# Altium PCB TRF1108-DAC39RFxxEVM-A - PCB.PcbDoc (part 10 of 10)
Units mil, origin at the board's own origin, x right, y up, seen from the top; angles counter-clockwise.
Board outline 4951.22 x 2726.56 mil, 16 copper layers (Top Layer, L2 GND1, L3 PWR1, L4 GND2, L5 PWR2, L6 GND3, L7 Ctrl Signal 1, L8 GND4, L9 GND5, L10 Ctrl Signal 2, L11 GND6, L12 PWR3, L13 GND7, L14 PWR4, L15 GND8, Bottom Layer), stack 80.2 mil thick; 705 components, 433 nets, 3633 pads, 1678 vias.
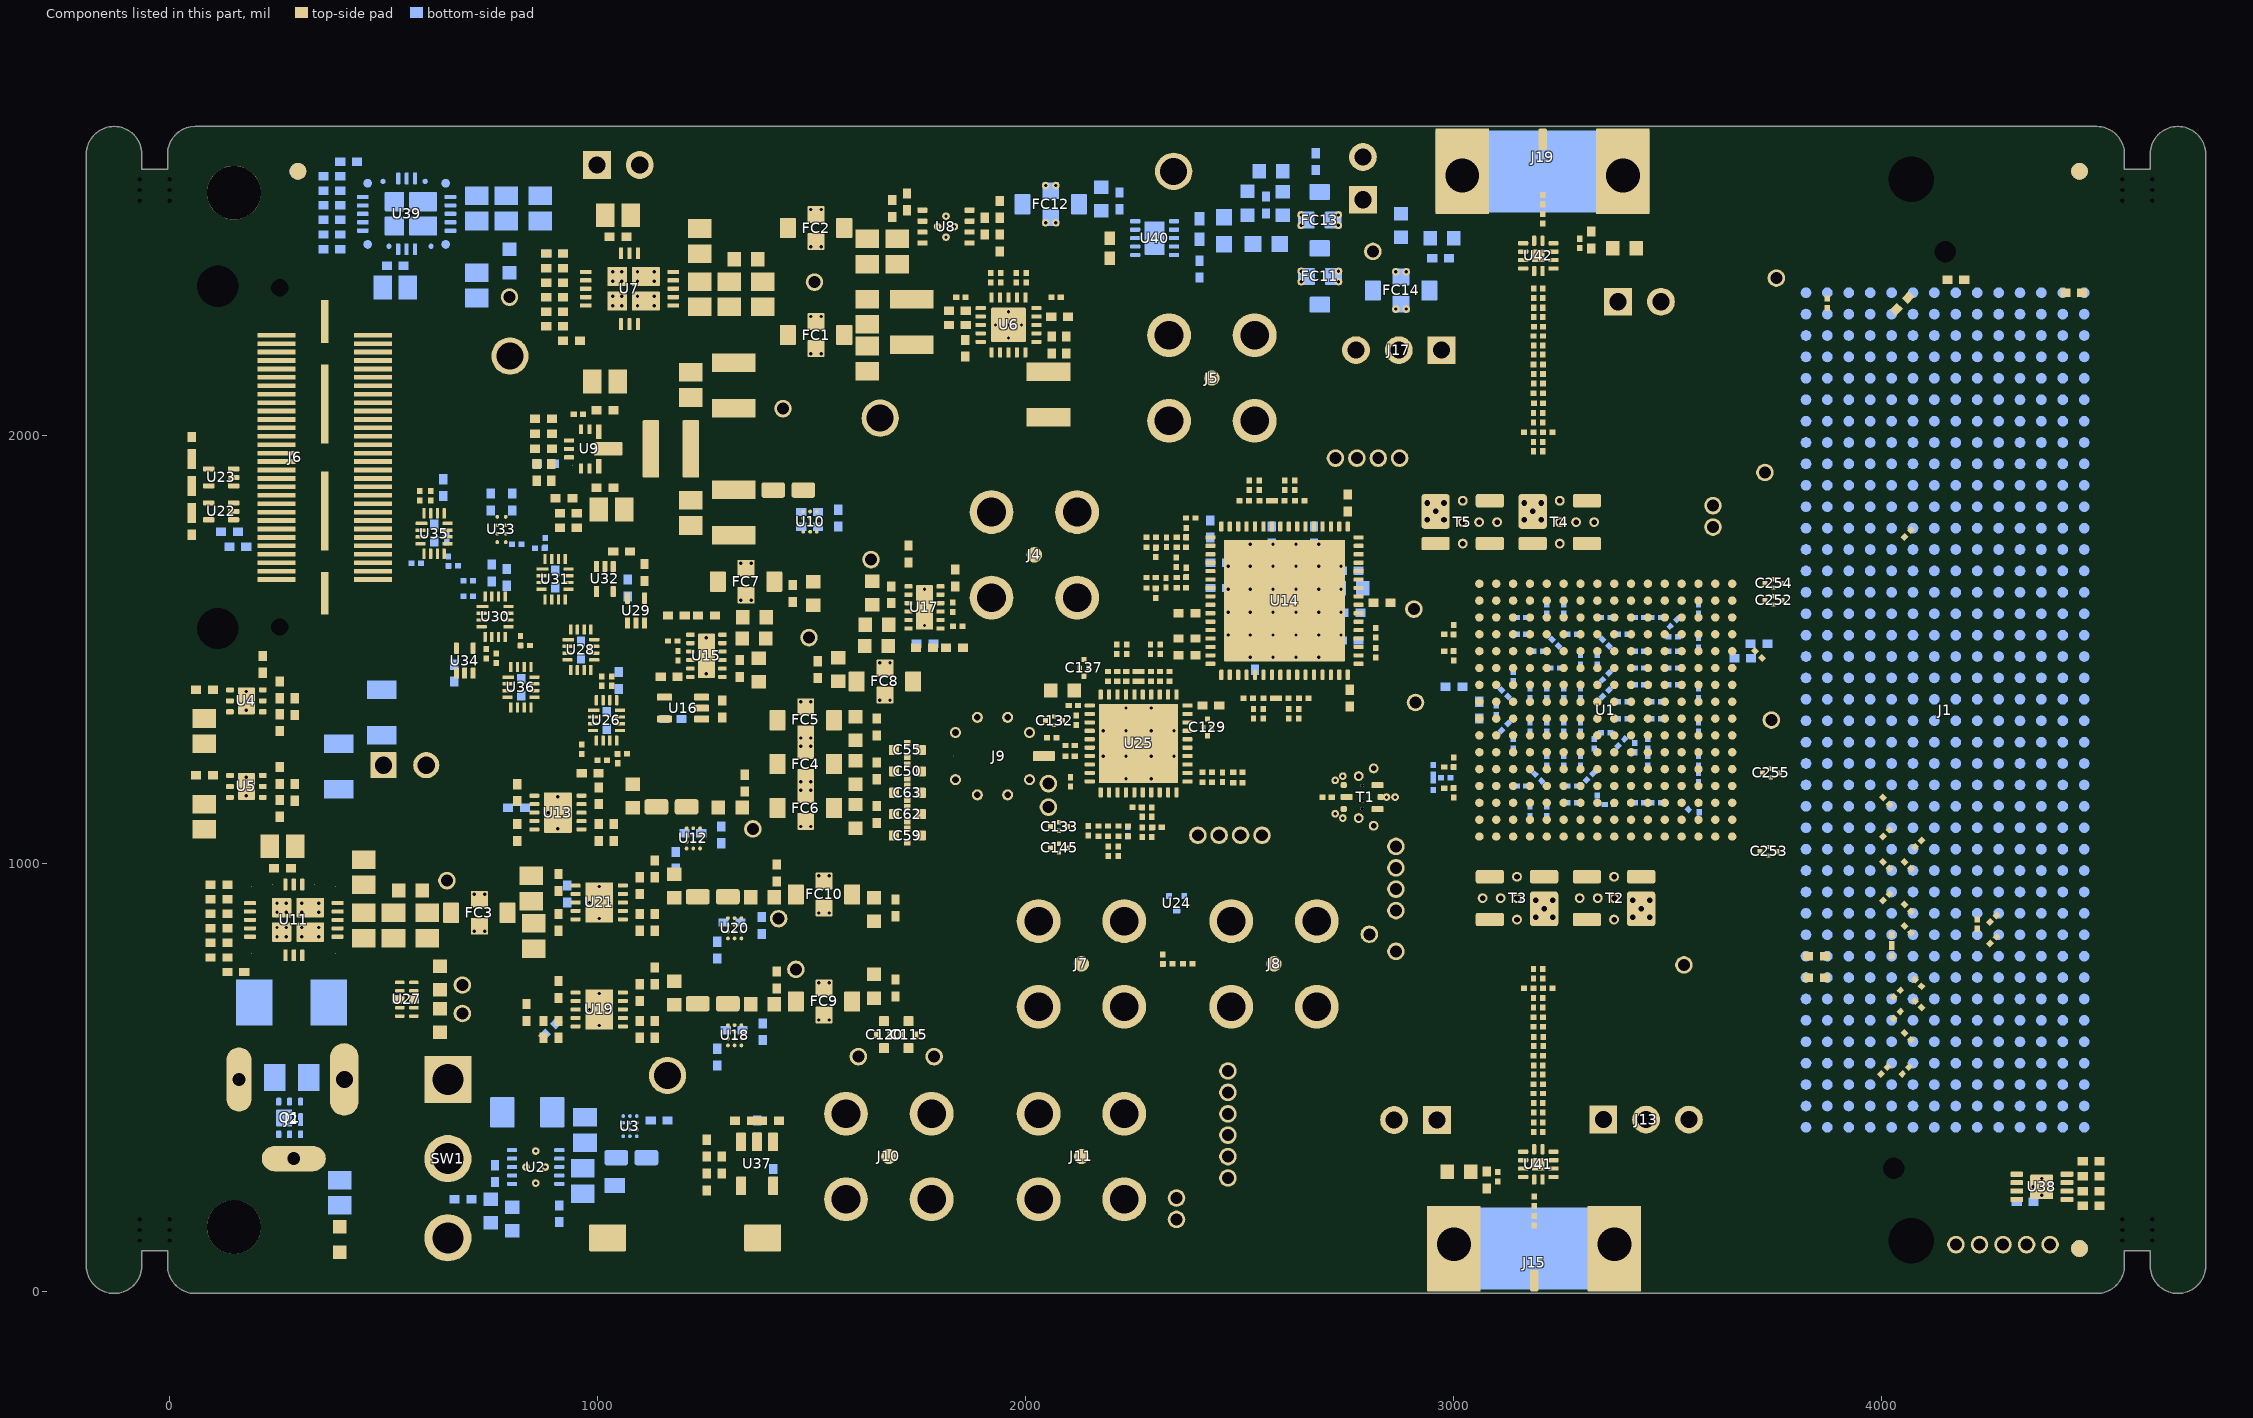
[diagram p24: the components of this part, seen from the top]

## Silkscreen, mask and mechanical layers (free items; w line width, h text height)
Top Overlay:
  lines w5: 1421.37,1569.44 1432.85,1557.95 1432.85,1508.72 ; 1497.99,1407.16 1508.32,1407.16 1510,1408.84 ; 1523.86,1520.73 1535.11,1520.73 1543.43,1529.05 ; 1848.55,1597.9 1873.98,1572.46 1873.98,1569.44 ; 2172.98,1419.4 2172.98,1464.4 2342.98,1464.4 ; 2242.76,1684.39 2254.63,1672.52 2264.21,1672.52 ; 2302.98,1984.4 2237.98,1984.4 2237.98,1909.4 2366.38,1909.4 ; 2372.98,1984.4 2482.98,1984.4 ; 2509.92,1909.4 2572.98,1909.4 2572.98,1984.4
  lines w6: 825.98,2352.4 845.98,2332.4 845.98,2259.4 854.98,2250.4 ; 3267.77,1965.4 3381.98,1965.4 3450.98,1896.4 3481.98,1896.4 ; 3296.89,2417.68 3307.19,2407.39 3307.19,2254.13 ; 3321.64,566.05 3487.05,566.05 3565.65,644.66 3632.53,644.66
  lines w7: 978.99,250.67 1165.44,250.67 ; 1974.16,1100.38 1998.36,1100.38 2024.75,1126.77 ; 2009.03,1126.77 2024.75,1126.77 ; 2024.75,1110 2024.75,1126.77 ; 2533.69,984.3 2533.69,1034.3 ; 2627.9,292.27 2681.61,292.38 ; 2629.25,342.38 2681.61,342.44 ; 2629.25,392.38 2681.61,392.43 ; 2791.92,912.21 2841.92,912.21 ; 2847.55,1979.23 2847.55,2029.23
  text "GND" at 2855.95,2642.27 h30
  text "Uninstalled=USB/Ext / Installed=FMC" at 1200,2600.51 h30
  text "5V" at 2853.2,2528.27 h30
  text "EVM  / Comms" at 450,2477.54 h50
  text "HSC1733" at 4174.55,2456.29 h50
  text "3P3V" at 2769.43,2275.32 h30 r90
  text "GND" at 2978.76,2275.32 h30 r90
  text "PD" at 2850.58,2270.37 h30 r90
  text "DAC39RFXX_TRF11XX_EVM / REVA   AMPS214" at 3643,2115 h44
  text "A" at 2240.96,1993.8 h30
  text "LMK" at 2923.65,1630.22 h30 r90
  text "A" at 2251.96,1474.76 h30
  text "LMX" at 2586,1051 h30
  text "DAC" at 2934,946 h30 r90
  text "SYNC" at 3856.18,817.26 h30
  text "PD" at 3460,477.75 h30 r90
  text "3P3V" at 3566.37,475.28 h30 r90
  text "GND" at 3360.62,474.87 h30 r90
  text "FMC SPI" at 2437.81,298.97 h30 r90
  text "FPGA GPIO" at 4156,46 h30
  text ".Layer_Name" at 750,-1333.99 h60
Bottom Overlay:
  circle w6: c3516.16,1203.77 r25
  circle w6: c1910.4,1143.27 r25
  circle w6: c2215.82,1930.09 r25
  circle w6: c3588.29,1455.01 r25
  lines w6: 294,2291 294,2563 333,2602 336,2602 337,2603 ; 1652.6,1963.18 1652.6,1810.66 1851.56,1810.66 ; 1652.6,2117.3 1652.6,2295.62 1673.91,2295.62 2289.52,2295.62 ; 1984.09,1810.66 2059.45,1810.66 ; 2203.99,1810.66 2325.25,1810.66 2325.25,1942.14 ; 2324.65,2097.08 2325.25,2153.75 ; 3080,1625 3635,1625 3635,1616.55 ; 1358.53,1164.2 1440.79,1164.2 1440.79,966.16 2011.16,966.16 2011.16,1437.26 2007.25,1437.26 1358.53,1437.26 1358.53,1164.2
  lines w7: 2504.64,290.77 2554.64,290.77 ; 2505.29,341.32 2555.29,341.32 ; 2505.29,391.42 2555.29,391.42 ; 2575,1095 2575,1145 ; 2785,915 2835,915 ; 2891,1981 2891,2031 ; 3080,1625 3080,1325 ; 3085,1325 3105,1325 3135,1355 3595,1355 3635,1355 ; 3095,1325 3080,1325 ; 3635,1616.55 3635,1355 ; 3080,1325 3080,1109.76 3080,1083.66 3635,1083.66 3635,1109.76 3635,1355
  text "A" at 2225.67,1915.66 h30
  text "LMK" at 2845.34,1880.38 h30
  text "A" at 3598.14,1440.58 h30
  text "B" at 3523.93,1188.96 h30
  text "B" at 1918.82,1128.28 h30
  text "LMX" at 2519,996 h30
  text "DAC" at 2901,941 h30 r270
  text "FMC SPI" at 2406,296 h30 r270
  text ".Layer_Name" at 577,-1358.49 h60
Top Paste:
  text ".Layer_Name" at 577,-1358.49 h60
Bottom Paste:
  text ".Layer_Name" at 577,-1358.49 h60
Top Solder:
  drawing of 40 lines, arcs and shapes, not listed
  text ".Layer_Name" at 577,-1358.49 h60
  text ".Layer_Name" at 577,-1358.49 h60
Bottom Solder:
  rectangle: 2957.44,1192.08 2965.94,1208.5
  region: 3403.51,1495.98 3403.72,1496.19 3419.73,1496.19 3419.73,1489.55 3414.36,1484.18 3403.5,1495.04 3403.5,1496.08
  text ".Layer_Name" at 577,-1358.49 h60
Drill Guide:
  text ".Layer_Name" at 797.87,-1357.4 h60
M1 Board Outline:
  lines w10: -130,0 ccw(c-130,60) -70,60 ; -130,2716.54 cw(c-130,2656.54) -70,2656.54 -70,2616.54 0,2616.54 0,2656.54 cw(c60,2656.54) 60,2716.54 4501.81,2716.54 cw(c4501.81,2656.53) 4561.81,2656.53 4561.81,2616.54 4631.81,2616.54 4631.81,2656.54 cw(c4691.81,2656.54) 4691.81,2716.54 ; -129.69,0 cw(c-129.69,60) -189.69,60 -189.69,2656.54 cw(c-129.69,2656.54) -129.69,2716.54 ; 4691.5,0 ccw(c4691.5,60) 4751.5,60 4751.5,2656.54 ccw(c4691.5,2656.54) 4691.5,2716.54 ; 4691.81,0 cw(c4691.81,60) 4631.81,60 ; -70,60 -70,100 0,100 0,60 ccw(c60,60) 60,0 4501.81,0 ccw(c4501.81,60) 4561.81,60 4561.81,100 4631.81,100 4631.81,60 ; -70,60 -70,60 ; -70,2529.73 -70,186.81 0,186.81 0,2529.73 -70,2529.73 ; -70,2529.73 -70,2529.73 ; 4631.81,60 4631.81,60 ; 4561.81,186.81 4561.81,2529.73 4631.81,2529.73 4631.81,186.81 4561.81,186.81
  text ".Layer_Name" at 577,-1358.49 h60
M2 Board Dimensions:
  rectangle: 63.78,-725 188.78,-600
  rectangle: 188.78,-850 563.78,-725
  lines w7: 63.78,-725 1063.78,-725 ; 188.78,-850 188.78,-600 ; 313.78,-850 313.78,-600 ; 563.78,-850 563.78,-600 ; 813.78,-850 813.78,-600 ; 63.78,-850 63.78,-600 1063.78,-600 1063.78,-850 63.78,-850
  text ".Layer_Name" at 577,-1358.49 h60
M3 3D STEP Top:
  text ".Layer_Name" at 577,-1358.49 h60
M4 3D STEP Bottom:
  text ".Layer_Name" at 577,-1358.49 h60
M5 Assembly Top:
  lines w10: -292,-1430.17 6308,-1430.17 ; -292,-1226.83 6310,-1226.83 ; -292,-1023.5 -292,-1633.5 3713,-1633.5 6310,-1633.5 6310,-1023.5 -291.5,-1023.5 -291.5,-1633.5 1284,-1633.5 ; 2173,-1633.5 2173,-1023.5 ; 3440,-1226.83 3440,-1023.5 ; 4280,-1226.83 4280,-1023.5 ; 4902,-1640 4902,-1437.17
  text "COMPONENTS MARKED 'DNP' SHOULD NOT BE POPULATED." at 1153.5,-818.5 h60
  text "ASSEMBLY VARIANT:" at 1153,-934 h60
  text ".VariantName" at 2189,-934 h60
  text "PCB VIEWED FROM TOP SIDE" at -228.5,-1155.67 h60
  text "BOARD #:" at 2248,-1155.67 h60
  text ".PRJ_Number" at 2793.5,-1155.67 h60
  text "REV:" at 3638,-1155.67 h60
  text ".PCB_Rev" at 3929.5,-1155.67 h60
  text "SVN REV:" at 4476,-1155.67 h60
  text ".VersionControl_RevNumber" at 4982,-1155.67 h60
  text "PLOT NAME =" at -228.5,-1564.34 h60
  text ".plot_File_Name" at 577,-1564.34 h60
  text "GENERATED    :" at 2250,-1564.34 h60
  text ".Print_Date" at 3119.5,-1564.34 h60
  text ".Print_Time" at 3848.5,-1564.34 h60
  text "TEXAS INSTRUMENTS" at 5113,-1564.34 h60
M6 Assembly Bottom:
  circle w10: c461.16,2587.83 r9.05
  lines w10: -292.5,-1227.33 6309.5,-1227.33 ; -290.5,-1430.67 6309.5,-1430.67 ; 1115.5,-1640.5 1115.5,-1437.67 ; 1737.5,-1227.33 1737.5,-1024 ; 2577.5,-1227.33 2577.5,-1024 ; 3844.5,-1634 3844.5,-1024 ; 4733.5,-1634 6309,-1634 6309,-1024 -292.5,-1024 -292.5,-1634 2304.5,-1634 6309.5,-1634 6309.5,-1024
  text "U24" at 2336.09,901.66 h12
  text "COMPONENTS MARKED 'DNP' SHOULD NOT BE POPULATED." at 6102,-818 h60
  text ".VariantName" at 5058,-934 h60
  text "ASSEMBLY VARIANT:" at 6097,-934 h60
  text ".VersionControl_RevNumber" at 1035.5,-1156.17 h60
  text "SVN REV:" at 1541.5,-1156.17 h60
  text ".PCB_Rev" at 2088,-1156.17 h60
  text "REV:" at 2379.5,-1156.17 h60
  text ".PRJ_Number" at 3224,-1156.17 h60
  text "BOARD #:" at 3769.5,-1156.17 h60
  text "PCB VIEWED FROM BOTTOM SIDE" at 6246,-1156.17 h60
  text "TEXAS INSTRUMENTS" at 904.5,-1564.84 h60
  text ".Print_Time" at 2169,-1564.84 h60
  text ".Print_Date" at 2898,-1564.84 h60
  text "GENERATED    :" at 3767.5,-1564.84 h60
  text ".plot_File_Name" at 5440.5,-1564.84 h60
  text "PLOT NAME =" at 6246,-1564.84 h60
M9 Title Sheet:
  drawing of 56 lines, arcs and shapes, not listed
  text "1" at -941.66,11381.39 h70
  text "2" at 2384,11381.39 h70
  text "3" at 5714,11381.39 h70
  text "4" at 9049,11381.39 h70
  text "5" at 12374,11381.39 h70
  text "6" at 15709,11381.39 h70
  text "A" at -2463,9603.39 h70
  text "A" at 17237,9603.39 h70
  text "B" at -2463,5853.39 h70
  text "B" at 17237,5853.39 h70
  text "C" at -2463,2103.39 h70
  text "C" at 17237,1906.54 h70
  text ".Layer_Name" at 577,-1358.49 h60
  text "D" at -2463,-1646.61 h70
  text "D" at 17237,-1646.61 h70
  text "PROJECT TITLE:" at 14143,-1731.61 h45
  text ".PRJ_Title" at 14193,-1864.94 h70
  text "DESIGNED FOR:" at 14143,-2032.61 h45
  text ".PRJ_Customer" at 14193,-2172.61 h70
  text "FILE NAME:" at 14143,-2332.61 h45
  text ".PCB_File_Name_No_Path" at 14193,-2452.61 h70
  text "Texas Instruments (TI) and/or its licensors do not warrant the accuracy or completeness of this specification" at 9173.5,-2614.45 h45
  text "ENGINEER:" at 14143,-2622.61 h45
  text "LAYOUT BY:" at 15648,-2622.61 h45
  text "or any information contained therein. TI and/or its licensors do not warrant that this design will meet" at 9128.51,-2727.11 h45
  text ".PRJ_Engineer" at 14193,-2777.6 h70
  text ".PCB_Layout" at 15698.5,-2777.6 h70
  text "the specifications, will be suitable for your application or fit for any particular purpose, or will operate in" at 9128.51,-2839.78 h45
  text "ALTIUM DESIGNER VERSION:" at 15648,-2932.61 h45
  text "an implementation. TI and/or its licensors do not warrant that the design is production worthy. You should" at 9128.51,-2952.44 h45
  text "completely validate and test your design implementation to confirm the system functionality for your application." at 9173.5,-3065.11 h45
  text ".print_Scale" at 14193,-3065.94 h70
  text ".Application_BuildNumber" at 15698.5,-3065.94 h70
  text "1" at -941.66,-3318.61 h70
  text "2" at 2384,-3318.61 h70
  text "3" at 5714,-3318.61 h70
  text "4" at 9049,-3318.61 h70
  text "5" at 12374,-3318.61 h70
  text "6" at 15709,-3318.61 h70
M10 Fab Notes:
  drawing of 246 lines, arcs and shapes, not listed
  text "NOTES: (UNLESS OTHERWISE SPECIFIED)" at -480.84,8498.11 h100
  text "1.FABRICATE PER IPC-6012A CLASS 2" at -480.84,8272.82 h100
  text "2.LAMINATE MATERIAL: MEGTRON6 & FR4-370HR" at -480.84,8047.53 h100
  text "IMPEDANCE TABLE" at 10010,8010 h100
  text "3.COPPER WEIGHT: SEE STACKUP" at -480.84,7822.24 h100
  text "SINGLE ENDED (50 OHM)" at 9760,7800 h60
  text "DIFF PAIR (100 OHM)" at 11650,7800 h60
  text "LAYERS" at 8799.36,7688.62 h60
  text "WIDTH" at 9848.99,7598.29 h60
  text "TOLERANCE" at 10628.48,7598.29 h60
  text "WIDTH/GAP" at 11550,7598.29 h60
  text "TOLERANCE" at 12429.48,7598.29 h60
  text "4.BOARD THICKNESS: 2MM +/- 10%" at -480.84,7580.29 h100
  text "TOP LAYER" at 8735.63,7396.99 h55
  text "10 MIL" at 9848.99,7385.33 h60
  text "6.25 MIL /3.5 MIL" at 11300,7385.33 h60
  text "+/-10%" at 10695.3,7380.33 h60
  text "+/-10%" at 12496.3,7380.33 h60
  text "5.NO OF LAYERS: 16 AS PER SUPPLIED ARTWORK" at -480.84,7355 h100
  text "L10 CTRL SIGNAL 2" at 8520.28,7190 h55
  text "-----" at 9848.99,7187.5 h60
  text "4 MIL /5 MIL" at 11439.95,7187.5 h60
  text "-----" at 10695.3,7182.5 h60
  text "+/-10%" at 12496.3,7182.5 h60
  text "6.SURFACE FINISH: ENIG" at -480.84,7129.71 h100
  text "BOTTOM LAYER" at 8662.32,7000 h55
  text "10 MIL" at 9848.99,6988.34 h60
  text "6.25 MIL /3.5 MIL" at 11300,6988.34 h60
  text "+/-10%" at 10700.29,6983.34 h60
  text "+/-10%" at 12496.3,6983.34 h60
  text "7.SOLDERMASK BOTH SIDES WITH LIQUID PHOTO IMAGEABLE (LPI) PER IPC-SM-840C" at -480.84,6904.42 h100
  text "COLOR:RED" at -480.84,6679.13 h100
  text "8.SILKSCREEN: BOTH SIDE WITH PERMANENT NON CONDUCTIVE WHITE EPOXY INK." at -480.84,6453.84 h100
  text "SILKSCREEN MAY BE TRIMMED OFF ANY SOLDERED ENTITY." at -480.84,6228.55 h100
  text "M10 Fab Notes" at 14099.69,6057.1 h60
  text "9.BOW AND TWIST NOT TO EXCEED 0.180MM (0.007\") PER INCH AS MEASURED PER IPC-TM-650." at -480.84,5986.6 h100
  text "DESIGN INFORMATION" at 15178.02,5939.98 h60
  text "MIN. TRACK WIDTH:" at 14533.46,5807.85 h60
  text "4" at 15629.7,5807.85 h60
  text "MIL" at 15784.46,5807.85 h60
  text "10.SOLDER MASK CLEARANCE IS GIVEN SAME AS PAD SIZE EXCEPT FOR NPTH AND FIDUCIALS." at -480.84,5761.32 h100
  text "MIN. CLEARANCE:" at 14533.46,5683.73 h60
  text "MIL" at 15784.46,5683.73 h60
  text "3.5" at 15575,5675 h60
  text "MIN. VIA PAD SIZE:" at 14533.46,5559.6 h60
  text "18" at 15599.71,5559.6 h60
  text "MIL" at 15784.46,5559.6 h60
  text "VENDOR SHALL OVERSIZE THE MASK CLEARANCES AS PER THE REQUIRED  MANUFACTURING CAPABILITIES," at -480.84,5536.03 h100
  text "0.05mm (2MIL)" at 15228.46,5429.7 h60
  text "MINIMUM ANNULAR RING" at 14204.23,5421.48 h60
  text "EXTERNAL" at 15936.46,5421.48 h60
  text "PER" at 14404.23,5311.35 h60
  text "IPC-D-275 CLASS 2 LEVEL C" at 14624.23,5311.35 h60
  text "11.100% CONTINUITY TESTING USING DATABASE NETLIST SHALL BE PERFORMED." at -493.74,5246.14 h100
  text "MIL, HOLES" at 16112.46,5210.87 h60
  text "+/-" at 15720,5202.29 h60
  text "+/-" at 16574,5202.29 h60
  text "REGISTRATION TOLERANCES:" at 14204.23,5201.22 h60
  text "METAL" at 15404,5201.22 h60
  text "5" at 15980.2,5201.22 h60
  text "3" at 16813.2,5201.22 h60
  text "MIL" at 16929.46,5201.22 h60
  text "HOLE SIZE TOLERANCE (UNLESS OTHERWISE SPECIFIED):" at 14204.23,5102.91 h60
  text "+/-" at 16574,5100.03 h60
  text "3" at 16813.2,5098.97 h60
  text "MIL" at 16929.46,5098.97 h60
  text "12.ALL INNER LAYER UNCONNECTED PADS SHALL BE REMOVED." at -493.74,5020.85 h100
  text "MATERIAL:" at 14129.46,4961.32 h60
  text "ISOLA FR4-370HR (or Equivalent)" at 15115.9,4832.8 h60
  text "X" at 14971.46,4824.81 h60
  text "FR-408" at 14550.46,4819.15 h60
  text "13.LOCAL FIDUCIALS MUST BE FREE OF ANY MARKINGS." at -493.74,4795.56 h100
  text "Isola I-Speed" at 15115.9,4635.95 h60
  text "Meg4" at 14550.46,4623.44 h60
  text "14.ALL VIAS ARE REQUIRED NON-CONDUCTIVE FILL AND PLATED OVER ON BOTH SIDES EXCEPT 10.1 MIL DRILL VIAS. UNLESS OTHERWISE MASK IS OPENED IN GERBERS" at -493.74,4570.28 h100
  text "X" at 14415.9,4440.64 h60
  text "Meg6 (or Equivalent)" at 14550.46,4426.59 h60
  text "15.BOARD DIMENSION: 115.87 MM X 69 MM." at -493.74,4344.99 h100
  text "OTHER" at 14590.46,4229.74 h60
  text "62 MIL (1.6mm) +/-10%" at 14870.56,4086.71 h60
  text "81 MIL  +/-10%" at 16446.53,4086.71 h60
  text "X" at 16040.7,4082.23 h60
  text "THICKNESS:" at 14204.23,4078.49 h60
  text "OTHER" at 16155.46,4078.49 h60
  text "TOLERANCE:" at 14204.23,3940.17 h60
  text "X" at 15052.46,3940.17 h60
  text "ANSI IPC-6012 TYPE 3 CLASS 2" at 15230.48,3940.17 h60
  text "OTHER +/-" at 15230.46,3795.99 h60
  text "BOW & TWIST:" at 14204.23,3650.8 h60
  text "X" at 15052.46,3650.8 h60
  text "ANSI IPC-6012 TYPE 3 CLASS 2" at 15230.48,3650.8 h60
  text "OTHER +/-" at 15230.46,3504.1 h60
  text "DRILLING:" at 14129.46,3373.48 h60
  text "NC_DRILL FILES" at 15890.46,3268.29 h60
  text "REFERENCE:" at 14204.23,3264.36 h60
  text "X" at 14861.46,3264.26 h60
  text "AS SHOWN" at 15039.46,3264.36 h60
  text "X" at 15762.46,3264.36 h60
  text "OTHER" at 16188.46,3122.1 h60
  text "PTH COPPER THICKNESS:" at 14203.91,3118.57 h60
  text "X" at 15343.14,3118.57 h60
  text "20-30 um" at 15471.14,3118.57 h60
  text "BOARD FINISH:" at 14129.46,2970.98 h60
  text "SILKSCREEN:" at 14284.68,2860.85 h60
  text "X" at 15242.46,2860.85 h60
  text "TOP" at 15359.46,2860.85 h60
  text "X" at 15752.46,2860.85 h60
  text "BOTTOM" at 15870.46,2860.85 h60
  text "X" at 15752.71,2709.61 h60
  text "WHITE" at 16227.99,2706.26 h60
  text "SILKSCREEN COLOR:" at 14284.68,2705.66 h60
  text "WHITE" at 15359.46,2705.66 h60
  text "OTHER" at 15870.46,2705.66 h60
  text "RED" at 16476.25,2568.34 h60
  text "X" at 15965.14,2565.63 h60
  text "GREEN" at 15490.46,2562.21 h60
  text "OTHER" at 16108.46,2562.21 h60
  text "SOLDER RESIST COLOR:" at 14284.68,2555.35 h60
  text "X" at 15372.46,2407.96 h60
  text "MATTE" at 15490.46,2407.96 h60
  text "SEMI-GLOSS" at 16108,2407.32 h60
  text "IMMERSION GOLD (ENIG)" at 15190.46,2235.19 h60
  text "ENEPIG" at 16528,2227.97 h60
  text "SURFACE FINISH:" at 14129.46,2226.97 h60
  text "X" at 15012.46,2226.97 h60
  text "IMM. TIN/SILVER OR EQUIV" at 14459,2089.65 h60
  text "HARD GOLD (30u)" at 15890.46,2085.72 h60
  text "OTHER" at 14484,1888.87 h60
  text "ARRAY/PANEL:" at 14129.46,1733.49 h60
  text "CUT AND TRIM PER M1 BOARD OUTLINE" at 15190.46,1725.27 h60
  text "N.C. ROUTE" at 15190.46,1589.3 h60
  text "X" at 15878.46,1589.3 h60
  text "V. SCORE" at 16056.46,1589.3 h60
  text "CERTIFICATION:" at 14129.46,1460.17 h60
  text "MATERIALS AND WORKMANSHIP FOR ALL PCBS" at 14854.46,1460.17 h60
  text "TO MEET OR EXCEED THE REQUIREMENTS OF:" at 14854.46,1366.11 h60
  text "X" at 14491.97,1237.48 h60
  text "ANSI IPC-A-600F CLASS ->" at 14619.96,1237.48 h60
  text "X" at 16267.97,1237.48 h60
  text "2" at 16377.96,1237.48 h60
  text "1" at 16062.96,1235.99 h60
  text "3" at 16731.96,1235.98 h60
  text "X" at 15303.97,1089.8 h60
  text "RoHS" at 15431.96,1089.8 h60
  text "OTHER" at 16076.36,1089.8 h60
  text "PER ORDER" at 16473.42,1089.8 h60
  text "ALL BOARDS MUST MEET OR EXCEED UL94-V0 REQUIREMENTS." at 14157,935.97 h60
  text "PCB MUST BEAR THE UL94V-0 UL REGISTERED MATERIAL ID NUMBER" at 14157,819.91 h60
  text "ADDITIONAL REQUIREMENTS:" at 14129.46,650.48 h60
  text "MICROSECTION:" at 14204.23,543.36 h60
  text "YES" at 15109.96,543.36 h60
  text "REQUIRED" at 15971.46,399.02 h60
  text "BARE BOARD ELEC. TEST:" at 14204.23,396.17 h60
  text "NONE" at 15509.96,396.17 h60
  text "X" at 15853.46,396.17 h60
  text "PER ORDER" at 16563.46,396.17 h60
  text "X" at 14245.08,205.71 h60
  text "16 MIL & SMALLER VIAS REQUIRE NON-CONDUCTIVE FILL AND PLANARIZE" at 14356.3,115.16 h59
  text "X" at 14252.07,10.12 h60
  text "OUTER LAYER TRACKS 10 MIL WIDE REQUIRE 50 OHM SINGLE-ENDED IMPEDANCE" at 14359.25,-95.47 h60
  text "X" at 14250.36,-196.63 h60
  text "OUTER LAYER TRACKS 6.25 MIL WIDE WITH 3.5 MIL AIR GAP REQUIRE 100 OHM DIFFERENTIAL IMPEDANCE" at 14359.25,-300.2 h60
  text "INNER LAYER XX & XX TRACKS XX MIL WIDE REQUIRE 50 OHM SINGLE-ENDED IMPEDANCE" at 14359.25,-504.92 h60
  text "X" at 14245.36,-606.63 h60
  text "INNER LAYER 10 TRACKS 4 MIL WIDE WITH   / 5 MIL AIR GAP REQUIRE 100 OHM DIFFERENTIAL IMPEDANCE" at 14345,-780 h60
  text ".Layer_Name" at 577,-1358.49 h60
M11 Gerber Information:
  lines w10: -292,-1430.17 6308,-1430.17 ; -292,-1226.83 6310,-1226.83 ; -292,-1023.5 -292,-1633.5 3713,-1633.5 6310,-1633.5 6310,-1023.5 -291.5,-1023.5 -291.5,-1633.5 1284,-1633.5 ; 2173,-1633.5 2173,-1023.5 ; 3440,-1226.83 3440,-1023.5 ; 4280,-1226.83 4280,-1023.5 ; 4902,-1640 4902,-1437.17
  text "ALL ARTWORK VIEWED FROM TOP SIDE" at -228.5,-1155.67 h60
  text "BOARD #:" at 2248,-1155.67 h60
  text ".PRJ_Number" at 2793.5,-1155.67 h60
  text "REV:" at 3638,-1155.67 h60
  text ".PCB_Rev" at 3929.5,-1155.67 h60
  text "SVN REV:" at 4476,-1155.67 h60
  text ".VersionControl_RevNumber" at 4982,-1155.67 h60
  text "LAYER NAME =" at -228.5,-1358.49 h60
  text "PLOT NAME =" at -228.5,-1564.34 h60
  text ".plot_File_Name" at 577,-1564.34 h60
  text "GENERATED    :" at 2250,-1564.34 h60
  text ".Print_Date" at 3119.5,-1564.34 h60
  text ".Print_Time" at 3848.5,-1564.34 h60
  text "TEXAS INSTRUMENTS" at 5113,-1564.34 h60
M12 Stackup:
  drawing of 971 lines, arcs and shapes, not listed
  text "Layer" at 9129.39,4130 h60
  text "Name" at 9539.31,4130 h60
  text "Material" at 10629,4130 h60
  text "Thickness" at 11488.77,4130 h60
  text "Constant" at 12138.6,4130 h60
  text "Board Layer Stack" at 12708.46,4130 h60
  text "Top Overlay" at 9539.31,4010 h60
  text "Top Solder" at 9539.31,3890 h60
  text "Solder Resist" at 10629,3890 h60
  text "0.40mil" at 11488.77,3890 h60
  text "3.5" at 12138.6,3890 h60
  text "1" at 9129.39,3770 h60
  text "Top Layer" at 9539.31,3770 h60
  text "1.40mil" at 11488.77,3770 h60
  text "Dielectric 1" at 9539.31,3650 h60
  text "Megtron6" at 10629,3650 h60
  text "4.90mil" at 11488.77,3650 h60
  text "3.34" at 12138.6,3650 h60
  text "2" at 9129.39,3530 h60
  text "L2 GND1" at 9539.31,3530 h60
  text "CF-004" at 10629,3530 h60
  text "1.40mil" at 11488.77,3530 h60
  text "Dielectric 2" at 9539.31,3410 h60
  text "FR4-370HR" at 10629,3410 h60
  text "3.00mil" at 11488.77,3410 h60
  text "3.72" at 12138.6,3410 h60
  text "3" at 9129.39,3290 h60
  text "L3 PWR1" at 9539.31,3290 h60
  text "CF-004" at 10629,3290 h60
  text "1.40mil" at 11488.77,3290 h60
  text "Dielectric 3" at 9539.31,3170 h60
  text "FR4-370HR" at 10629,3170 h60
  text "3.00mil" at 11488.77,3170 h60
  text "3.72" at 12138.6,3170 h60
  text "4" at 9129.39,3050 h60
  text "L4 GND2" at 9539.31,3050 h60
  text "CF-004" at 10629,3050 h60
  text "1.40mil" at 11488.77,3050 h60
  text "Dielectric 4" at 9539.31,2930 h60
  text "FR4-370HR" at 10629,2930 h60
  text "3.00mil" at 11488.77,2930 h60
  text "3.86" at 12138.6,2930 h60
  text "5" at 9129.39,2810 h60
  text "L5 PWR2" at 9539.31,2810 h60
  text "CF-004" at 10629,2810 h60
  text "1.40mil" at 11488.77,2810 h60
  text "Dielectric 5" at 9539.31,2690 h60
  text "FR4-370HR" at 10629,2690 h60
  text "3.00mil" at 11488.77,2690 h60
  text "3.72" at 12138.6,2690 h60
  text "6" at 9129.39,2570 h60
  text "L6 GND3" at 9539.31,2570 h60
  text "CF-004" at 10629,2570 h60
  text "1.40mil" at 11488.77,2570 h60
  text "Dielectric 6" at 9539.31,2450 h60
  text "FR4-370HR" at 10629,2450 h60
  text "3.00mil" at 11488.77,2450 h60
  text "3.86" at 12138.6,2450 h60
  text "7" at 9129.39,2330 h60
  text "L7 Ctrl Signal 1" at 9539.31,2330 h60
  text "CF-004" at 10629,2330 h60
  text "1.40mil" at 11488.77,2330 h60
  text "Dielectric 8" at 9539.31,2210 h60
  text "FR4-370HR" at 10629,2210 h60
  text "3.00mil" at 11488.77,2210 h60
  text "3.72" at 12138.6,2210 h60
  text "Dielectric 7" at 9539.31,2090 h60
  text "FR4-370HR" at 10629,2090 h60
  text "3.00mil" at 11488.77,2090 h60
  text "3.72" at 12138.6,2090 h60
  text "8" at 9129.39,1970 h60
  text "L8 GND4" at 9539.31,1970 h60
  text "CF-004" at 10629,1970 h60
  text "1.40mil" at 11488.77,1970 h60
  text "Dielectric 9" at 9539.31,1850 h60
  text "FR4-370HR" at 10629,1850 h60
  text "6.00mil" at 11488.77,1850 h60
  text "3.86" at 12138.6,1850 h60
  text "9" at 9129.39,1730 h60
  text "L9 GND5" at 9539.31,1730 h60
  text "CF-004" at 10629,1730 h60
  text "1.40mil" at 11488.77,1730 h60
  text "Dielectric 11" at 9539.31,1610 h60
  text "FR4-370HR" at 10629,1610 h60
  text "3.00mil" at 11488.77,1610 h60
  text "3.72" at 12138.6,1610 h60
  text "Dielectric 10" at 9539.31,1490 h60
  text "FR4-370HR" at 10629,1490 h60
  text "3.00mil" at 11488.77,1490 h60
  text "3.72" at 12138.6,1490 h60
  text "10" at 9129.39,1370 h60
  text "L10 Ctrl Signal 2" at 9539.31,1370 h60
  text "CF-004" at 10629,1370 h60
  text "1.40mil" at 11488.77,1370 h60
  text "Dielectric 12" at 9539.31,1250 h60
  text "FR4-370HR" at 10629,1250 h60
  text "3.00mil" at 11488.77,1250 h60
  text "3.86" at 12138.6,1250 h60
  text "11" at 9129.39,1130 h60
  text "L11 GND6" at 9539.31,1130 h60
  text "CF-004" at 10629,1130 h60
  text "1.40mil" at 11488.77,1130 h60
  text "Dielectric 13" at 9539.31,1010 h60
  text "FR4-370HR" at 10629,1010 h60
  text "3.00mil" at 11488.77,1010 h60
  text "3.72" at 12138.6,1010 h60
  text "12" at 9129.39,890 h60
  text "L12 PWR3" at 9539.31,890 h60
  text "CF-004" at 10629,890 h60
  text "1.40mil" at 11488.77,890 h60
  text "Dielectric 14" at 9539.31,770 h60
  text "FR4-370HR" at 10629,770 h60
  text "3.00mil" at 11488.77,770 h60
  text "3.86" at 12138.6,770 h60
  text "13" at 9129.39,650 h60
  text "L13 GND7" at 9539.31,650 h60
  text "CF-004" at 10629,650 h60
  text "1.40mil" at 11488.77,650 h60
  text "Dielectric 15" at 9539.31,530 h60
  text "FR4-370HR" at 10629,530 h60
  text "3.00mil" at 11488.77,530 h60
  text "3.72" at 12138.6,530 h60
  text "14" at 9129.39,410 h60
  text "L14 PWR4" at 9539.31,410 h60
  text "CF-004" at 10629,410 h60
  text "1.40mil" at 11488.77,410 h60
  text "Dielectric 16" at 9539.31,290 h60
  text "FR4-370HR" at 10629,290 h60
  text "3.00mil" at 11488.77,290 h60
  text "3.72" at 12138.6,290 h60
  text "15" at 9129.39,170 h60
  text "L15 GND8" at 9539.31,170 h60
  text "CF-004" at 10629,170 h60
  text "1.40mil" at 11488.77,170 h60
  text "Dielectric 17" at 9539.31,50 h60
  text "Megtron6" at 10629,50 h60
  text "4.90mil" at 11488.77,50 h60
  text "3.34" at 12138.6,50 h60
  text "16" at 9129.39,-70 h60
  text "Bottom Layer" at 9539.31,-70 h60
  text "1.40mil" at 11488.77,-70 h60
  text "Bottom Solder" at 9539.31,-190 h60
  text "Solder Resist" at 10629,-190 h60
  text "0.40mil" at 11488.77,-190 h60
  text "3.5" at 12138.6,-190 h60
  text "Bottom Overlay" at 9539.31,-310 h60
  text "Total board thickness:" at 9129.39,-430 h60
  text "81.00mil" at 11488.77,-430 h60
  text ".Layer_Name" at 577,-1358.49 h60
M13 Component Bodies Top:
  text ".Layer_Name" at 577,-1358.49 h60
M14 Component Bodies Bottom:
  text ".Layer_Name" at 577,-1358.49 h60
M15 Courtyards Top:
  text ".Layer_Name" at 577,-1358.49 h60
M16 Courtyards Bottom:
  text ".Layer_Name" at 577,-1358.49 h60
Drill Drawing:
  drawing of 172 lines, arcs and shapes, not listed
  text "Symbol" at 5817.36,2857.52 h72
  text "Count" at 6117.92,2857.52 h72
  text "Hole Size" at 6450.09,2857.52 h72
  text "Plated" at 7040,2857.52 h72
  text "Hole Type" at 7299.14,2857.52 h72
  text "Drill Layer Pair" at 7674.3,2857.52 h72
  text "Hole Tolerance" at 8398.63,2857.52 h72
  text "194" at 6117.92,2733.2 h60
  text "7.87mil (0.200mm)" at 6450.09,2733.2 h60
  text "PTH" at 7040,2733.2 h60
  text "Round" at 7299.14,2733.2 h60
  text "Top Layer - Bottom Layer" at 7674.3,2733.2 h60
  text "+/-3.00mil" at 8398.63,2733.2 h60
  text "E" at 5792.07,2723.21 h55.25
  text "1479" at 6117.92,2608.88 h60
  text "8.00mil (0.203mm)" at 6450.09,2608.88 h60
  text "PTH" at 7040,2608.88 h60
  text "Round" at 7299.14,2608.88 h60
  text "Top Layer - Bottom Layer" at 7674.3,2608.88 h60
  text "+/-3.00mil" at 8398.63,2608.88 h60
  text "C" at 5792.07,2598.89 h55.25
  text "24" at 6117.92,2484.56 h60
  text "10.00mil (0.254mm)" at 6450.09,2484.56 h60
  text "NPTH" at 7040,2484.56 h60
  text "Round" at 7299.14,2484.56 h60
  text "Top Layer - Bottom Layer" at 7674.3,2484.56 h60
  text "+/-2.00mil" at 8398.63,2484.56 h60
  text "187" at 6117.92,2360.24 h60
  text "10.01mil (0.254mm)" at 6450.09,2360.24 h60
  text "PTH" at 7040,2360.24 h60
  text "Round" at 7299.14,2360.24 h60
  text "Top Layer - Bottom Layer" at 7674.3,2360.24 h60
  text "+/-3.00mil" at 8398.63,2360.24 h60
  text "40" at 6117.92,2235.92 h60
  text "12.99mil (0.330mm)" at 6450.09,2235.92 h60
  text "PTH" at 7040,2235.92 h60
  text "Round" at 7299.14,2235.92 h60
  text "Top Layer - Bottom Layer" at 7674.3,2235.92 h60
  text "+/-3.00mil" at 8398.63,2235.92 h60
  text "4" at 6117.92,2111.6 h60
  text "13.00mil (0.330mm)" at 6450.09,2111.6 h60
  text "PTH" at 7040,2111.6 h60
  text "Round" at 7299.14,2111.6 h60
  text "Top Layer - Bottom Layer" at 7674.3,2111.6 h60
  text "+/-3.00mil" at 8398.63,2111.6 h60
  text "8" at 6117.92,1987.28 h60
  text "15.75mil (0.400mm)" at 6450.09,1987.28 h60
  text "PTH" at 7040,1987.28 h60
  text "Round" at 7299.14,1987.28 h60
  text "Top Layer - Bottom Layer" at 7674.3,1987.28 h60
  text "+/-3.00mil" at 8398.63,1987.28 h60
  text "D" at 5792.07,1977.29 h55.25
  text "51" at 6117.92,1862.96 h60
  text "28.00mil (0.711mm)" at 6450.09,1862.96 h60
  text "PTH" at 7040,1862.96 h60
  text "Round" at 7299.14,1862.96 h60
  text "Top Layer - Bottom Layer" at 7674.3,1862.96 h60
  text "+/-3.00mil" at 8398.63,1862.96 h60
  text "2" at 6117.92,1738.64 h60
  text "29.92mil (0.760mm)" at 6450.09,1738.64 h60
  text "PTH" at 7040,1738.64 h60
  text "Slot" at 7299.14,1738.64 h60
  text "Top Layer - Bottom Layer" at 7674.3,1738.64 h60
  text "+/-3.00mil" at 8398.63,1738.64 h60
  text "1" at 6117.92,1614.32 h60
  text "39.76mil (1.010mm)" at 6450.09,1614.32 h60
  text "PTH" at 7040,1614.32 h60
  text "Slot" at 7299.14,1614.32 h60
  text "Top Layer - Bottom Layer" at 7674.3,1614.32 h60
  text "+/-3.00mil" at 8398.63,1614.32 h60
  text "14" at 6117.92,1490 h60
  text "40.00mil (1.016mm)" at 6450.09,1490 h60
  text "PTH" at 7040,1490 h60
  text "Round" at 7299.14,1490 h60
  text "Top Layer - Bottom Layer" at 7674.3,1490 h60
  text "+/-3.00mil" at 8398.63,1490 h60
  text "2" at 6117.92,1365.68 h60
  text "40.16mil (1.020mm)" at 6450.09,1365.68 h60
  text "NPTH" at 7040,1365.68 h60
  text "Round" at 7299.14,1365.68 h60
  text "Top Layer - Bottom Layer" at 7674.3,1365.68 h60
  text "+/-2.00mil" at 8398.63,1365.68 h60
  text "2" at 6117.92,1241.36 h60
  text "40.16mil (1.020mm)" at 6450.09,1241.36 h60
  text "PTH" at 7040,1241.36 h60
  text "Round" at 7299.14,1241.36 h60
  text "Top Layer - Bottom Layer" at 7674.3,1241.36 h60
  text "+/-3.00mil" at 8398.63,1241.36 h60
  text "2" at 6117.92,1117.04 h60
  text "50.00mil (1.270mm)" at 6450.09,1117.04 h60
  text "NPTH" at 7040,1117.04 h60
  text "Round" at 7299.14,1117.04 h60
  text "Top Layer - Bottom Layer" at 7674.3,1117.04 h60
  text "+/-2.00mil" at 8398.63,1117.04 h60
  text "A" at 5792.07,1107.05 h55.25
  text "4" at 6117.92,992.72 h60
  text "63.00mil (1.600mm)" at 6450.09,992.72 h60
  text "PTH" at 7040,992.72 h60
  text "Round" at 7299.14,992.72 h60
  text "Top Layer - Bottom Layer" at 7674.3,992.72 h60
  text "+/-3.00mil" at 8398.63,992.72 h60
  text "24" at 6117.92,868.4 h60
  text "66.93mil (1.700mm)" at 6450.09,868.4 h60
  text "PTH" at 7040,868.4 h60
  text "Round" at 7299.14,868.4 h60
  text "Top Layer - Bottom Layer" at 7674.3,868.4 h60
  text "+/-3.00mil" at 8398.63,868.4 h60
  text "3" at 6117.92,744.08 h60
  text "72.84mil (1.850mm)" at 6450.09,744.08 h60
  text "PTH" at 7040,744.08 h60
  text "Round" at 7299.14,744.08 h60
  text "Top Layer - Bottom Layer" at 7674.3,744.08 h60
  text "+/-3.00mil" at 8398.63,744.08 h60
  text "4" at 6117.92,619.76 h60
  text "79.00mil (2.007mm)" at 6450.09,619.76 h60
  text "PTH" at 7040,619.76 h60
  text "Round" at 7299.14,619.76 h60
  text "Top Layer - Bottom Layer" at 7674.3,619.76 h60
  text "+/-3.00mil" at 8398.63,619.76 h60
  text "B" at 5792.07,609.77 h55.25
  text "2" at 6117.92,495.44 h60
  text "96.46mil (2.450mm)" at 6450.09,495.44 h60
  text "NPTH" at 7040,495.44 h60
  text "Round" at 7299.14,495.44 h60
  text "Top Layer - Bottom Layer" at 7674.3,495.44 h60
  text "+/-2.00mil" at 8398.63,495.44 h60
  text "2" at 6117.92,371.12 h60
  text "105.91mil (2.690mm)" at 6450.09,371.12 h60
  text "NPTH" at 7040,371.12 h60
  text "Round" at 7299.14,371.12 h60
  text "Top Layer - Bottom Layer" at 7674.3,371.12 h60
  text "+/-2.00mil" at 8398.63,371.12 h60
  text "G" at 5792.07,361.13 h55.25
  text "2" at 6117.92,246.8 h60
  text "125.98mil (3.200mm)" at 6450.09,246.8 h60
  text "NPTH" at 7040,246.8 h60
  text "Round" at 7299.14,246.8 h60
  text "Top Layer - Bottom Layer" at 7674.3,246.8 h60
  text "+/-2.00mil" at 8398.63,246.8 h60
  text "F" at 5792.07,236.81 h55.25
  text "2051 Total" at 6117.92,122.48 h60
  text "Slot definitions :" at 5817.36,35.46 h60
  text "Routed Path Length" at 6268.07,35.46 h60
  text "= Calculated from tool start centre position to tool end centre position." at 6807.81,35.46 h60
  text "Hole Length" at 6268.07,-14.27 h60
  text "= Routed Path Length + Tool Size = Slot length as defined in the PCB layout" at 6608.01,-14.27 h60
  text ".Layer_Name" at 586,-1325.49 h60
M17 Embedded Cavity:
  text ".Layer_Name" at 577,-1358.49 h60
M18 Embedded Assembly:
  text ".Layer_Name" at 577,-1358.49 h60
M19 Embedded Keepout:
  text ".Layer_Name" at 567,-1358.49 h60

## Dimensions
4691.5,60 to 4860,-110 on M2 Board Dimensions
4501.81,2656.53 to 4690,2840 on M2 Board Dimensions
0,100 to -70,100 on M2 Board Dimensions
-70,186.81 to -70,100 on M2 Board Dimensions
60,2716.53 to 60,0 on M2 Board Dimensions
4561.81,100 to 0,100 on M2 Board Dimensions
63.78,-850 to 1063.78,-850 on M2 Board Dimensions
